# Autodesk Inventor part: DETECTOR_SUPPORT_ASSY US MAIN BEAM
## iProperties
Shininess: 64.0
Length Units: 11272
Angle Units: 11279
Time Units: 11290
Mass Units: 11286
Length Display Precision: 3
Angle Display Precision: 2
Compacted: True
Part Number: DETECTOR_SUPPORT_ASSY US MAIN BEAM
Document SubType Name: Modeling
Created: 2004-08
Designer: John Blackburn
Material: MILD_STEEL
Manufacturer: Standard
Standards Organization: Custom
Density: 0.0
Volumn: 0.0
Area: 0.0
PropertySet Name: Model Information
Control State: 0
Master: False
Checked Out: False
Author: John Blackburn
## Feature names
1. ExtrusionMidplane1
2. ExtrusionThru1
3. ExtrusionThru2
4. ExtrusionThru3
5. ExtrusionThru4
6. ExtrusionThru5
7. ExtrusionThru6
8. ExtrusionThru7
